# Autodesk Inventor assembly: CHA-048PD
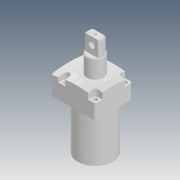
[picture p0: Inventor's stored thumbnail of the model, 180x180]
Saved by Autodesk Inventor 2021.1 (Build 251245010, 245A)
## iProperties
Created: 2018-12
Part Number: CHA-048PD
Description: STEP AP214
Document SubType Name: Assembly
Designer: user
Title: CHA-048PD.STEP
Revision Number: ÈÎºÎ
Sending System: SolidWorks 2016
Preprocessor: SwSTEP 2.0
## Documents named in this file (4)
- D:\Vault_2016\Projekty\Clamptek\Hydraulic\CHA-P\Inventor\CHA-048PD\CHA-048PD.iam
- D:\Vault_2016\Projekty\Clamptek\Hydraulic\CHA-P\Inventor\CHA-048PD\CHA-048P(BT).ipt
- D:\Vault_2016\Projekty\Clamptek\Hydraulic\CHA-P\Inventor\CHA-048PD\¶ÂÍ·G8-1.ipt
- D:\Vault_2016\Projekty\Clamptek\Hydraulic\CHA-P\Inventor\CHA-048PD\CHA-048PD(HSG).ipt
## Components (4 placed, 4 different names)
1. CHA-048P(BT)_1
2. ¶ÂÍ·G8-1_2
3. ¶ÂÍ·G8-1_3
4. CHA-048PD(HSG)_4
